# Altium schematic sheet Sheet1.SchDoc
size A4
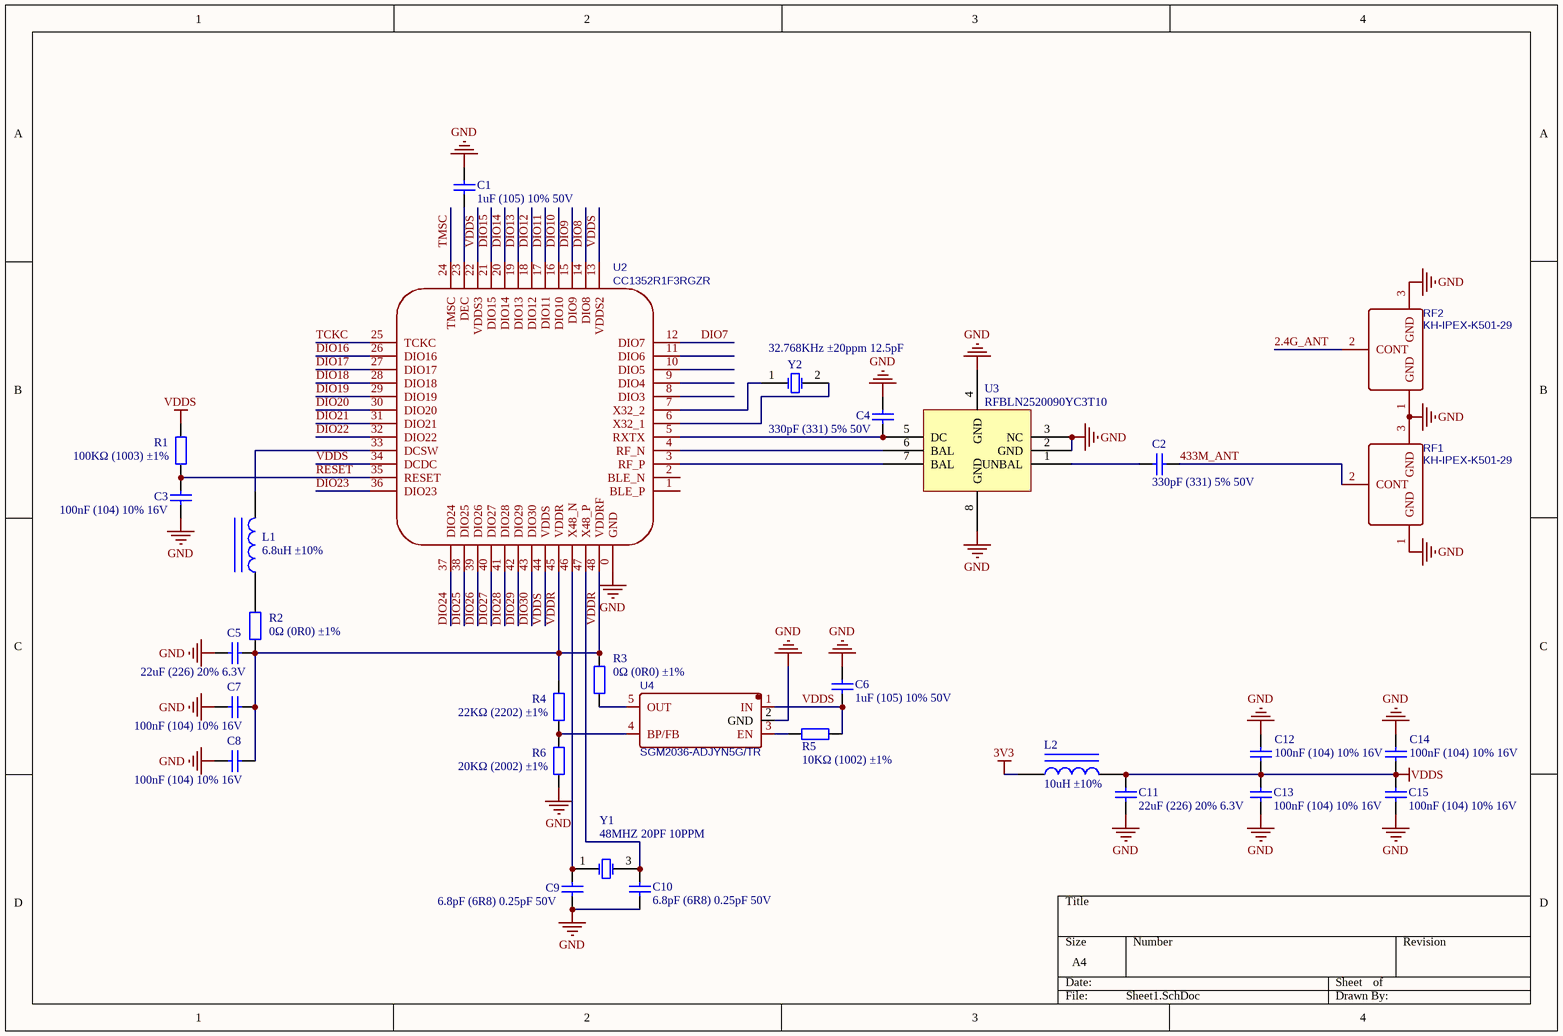
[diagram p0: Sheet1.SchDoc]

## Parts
C1  1uF (105) 10% 50V  [0603_C]
C2  330pF (331) 5% 50V  [0402_C]
C3  100nF (104) 10% 16V  [0402_C]
C4  330pF (331) 5% 50V  [0402_C]
C5  22uF (226) 20% 6.3V  [0603_C]
C6  1uF (105) 10% 50V  [0603_C]
C7  100nF (104) 10% 16V  [0402_C]
C8  100nF (104) 10% 16V  [0402_C]
C9  6.8pF (6R8) 0.25pF 50V  [0402_C]
C10  6.8pF (6R8) 0.25pF 50V  [0402_C]
C11  22uF (226) 20% 6.3V  [0603_C]
C12  100nF (104) 10% 16V  [0402_C]
C13  100nF (104) 10% 16V  [0402_C]
C14  100nF (104) 10% 16V  [0402_C]
C15  100nF (104) 10% 16V  [0402_C]
L1  6.8uH ±10%  [0603_L]
L2  10uH ±10%  [0603_L]
R1  100KΩ (1003) ±1%  [0402_R]
R2  0Ω (0R0) ±1%  [0402_R]
R3  0Ω (0R0) ±1%  [0402_R]
R4  22KΩ (2202) ±1%  [0402_R]
R5  10KΩ (1002) ±1%  [0402_R]
R6  20KΩ (2002) ±1%  [0402_R]
RF1  KH-IPEX-K501-29  [ANT-SMD_KH-IPEX-K501-29]
RF2  KH-IPEX-K501-29  [ANT-SMD_KH-IPEX-K501-29]
U2  CC1352R1F3RGZR  [QFN48]
U3  RFBLN2520090YC3T10  [FILTER-SMD_8P-L2.5-W2.0-BL]
U4  SGM2036-ADJYN5G/TR  [SOT-23-5_L3.0-W1.7-P0.95-LS2.8-BR]
Y1  48MHZ 20PF 10PPM  [SMD-3225_4P]
Y2  32.768KHz ±20ppm 12.5pF  [SMD-3215_2P FC - 135]

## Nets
3V3: L2.1
GND: C1.2 C3.1 C4.2 C5.2 C6.1 C7.2 C8.2 C9.1 C10.1 C11.2 C12.1 C13.2 C14.1 C15.2 R6.1 RF1.1(GND) RF1.3(GND) RF2.1(GND) RF2.3(GND) U2.0(GND) U3.2(GND) U3.3(NC) U3.4(GND) U3.8(GND) U4.2(GND)
VDDS: C6.2 C11.1 C12.2 C13.1 C14.2 C15.1 L2.2 R1.2 R5.2 U2.13(VDDS2) U2.22(VDDS3) U2.34(DCDC) U2.44(VDDS) U4.1(IN)
2.4G_ANT: RF2.2(CONT)
433M_ANT: C2.1 RF1.2(CONT)
DIO7: U2.12(DIO7)
DIO8: U2.14(DIO8)
DIO9: U2.15(DIO9)
DIO10: U2.16(DIO10)
DIO11: U2.17(DIO11)
DIO12: U2.18(DIO12)
DIO13: U2.19(DIO13)
DIO14: U2.20(DIO14)
DIO15: U2.21(DIO15)
DIO16: U2.26(DIO16)
DIO17: U2.27(DIO17)
DIO18: U2.28(DIO18)
DIO19: U2.29(DIO19)
DIO20: U2.30(DIO20)
DIO21: U2.31(DIO21)
DIO22: U2.32(DIO22)
DIO23: U2.36(DIO23)
DIO24: U2.37(DIO24)
DIO25: U2.38(DIO25)
DIO26: U2.39(DIO26)
DIO27: U2.40(DIO27)
DIO28: U2.41(DIO28)
DIO29: U2.42(DIO29)
DIO30: U2.43(DIO30)
RESET: C3.2 R1.1 U2.35(RESET)
TCKC: U2.25(TCKC)
TMSC: U2.24(TMSC)
VDDR: C5.1 C7.1 C8.1 R2.1 R3.2 R4.2 U2.45(VDDR) U2.48(VDDRF)
NetC1_1: C1.1 U2.23(DEC)
NetC2_2: C2.2 U3.1(UNBAL)
NetC4_1: C4.1 U2.5(RXTX) U3.5(DC)
NetC9_2: C9.2 U2.46(X48_N) Y1.1(OSC1)
NetC10_2: C10.2 U2.47(X48_P) Y1.3(OSC2)
NetL1_1: L1.1 R2.2
NetL1_2: L1.2 U2.33(DCSW)
NetR3_1: R3.1 U4.5(OUT)
NetR4_1: R4.1 R6.2 U4.4(BP/FB)
NetR5_1: R5.1 U4.3(EN)
NetU2_3: U2.3(RF_P) U3.7(BAL)
NetU2_4: U2.4(RF_N) U3.6(BAL)
NetU2_6: U2.6(X32_1) Y2.2(OSC2)
NetU2_7: U2.7(X32_2) Y2.1(OSC1)

Not connected (* = marked no-connect by the designer): U2 1(BLE_P) 2(BLE_N) 8(DIO3) 9(DIO4) 10(DIO5) 11(DIO6)

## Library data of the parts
C1 C6 = 0603 1uF (105) 10% 50V: 贴片电容
C2 C4 = 0402 330pF (331) 5% 50V: 贴片电容
C3 C7 C8 C12-C15 = 0402 100nF (104) 10% 16V: 贴片电容
C5 C11 = 0603 22uF (226) 20% 6.3V: 贴片电容
C9 C10 = 0402 6.8pF (6R8) 0.25pF 50V: 贴片电容
L1 = 0603 4.7uH 10%: 贴片电感
L2 = 0603 10uH 10%: 贴片电感
R1 = 0402 100KΩ (1003) 1%: 贴片电阻
R2 R3 = 0402 0Ω (0R0) 1%: 贴片电阻
R4 = 0402 22KΩ (2202) 1%: 贴片电阻
R5 = 0402 10KΩ (1002) 1%: 贴片电阻
R6 = 0402 20KΩ (2002) 1%: 贴片电阻
RF1 RF2 = KH-IPEX-K501-29: BOM_Manufacturer: Shenzhen Kinghelm Elec; Contributor: LCSC
U2 = CC1352R1F3RGZR: BOM_Manufacturer: TI; Contributor: sunwf
U4 = SGM2036-ADJYN5G/TR: BOM_Manufacturer: SGMICRO; Contributor: LCSC; SMT Type: Extend
Y1 = SMD-3225_4P  12MHZ 20PF 10PPM: 贴片晶振
Y2 = SMD-3215_2P 32.768KHz 20ppm 12.5pF: 贴片晶振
